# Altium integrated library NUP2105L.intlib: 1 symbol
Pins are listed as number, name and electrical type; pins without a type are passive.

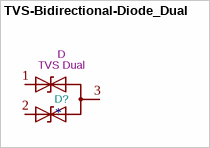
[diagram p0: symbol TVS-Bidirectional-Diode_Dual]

## TVS-Bidirectional-Diode_Dual
designator D?  value TVS Dual  Reference: D
ki_keywords: TVS Dual Diode
footprint SOT-23 (SOT23, 3-Leads, IPC Medium Density, TO-236)
pins: 1, 2, 3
